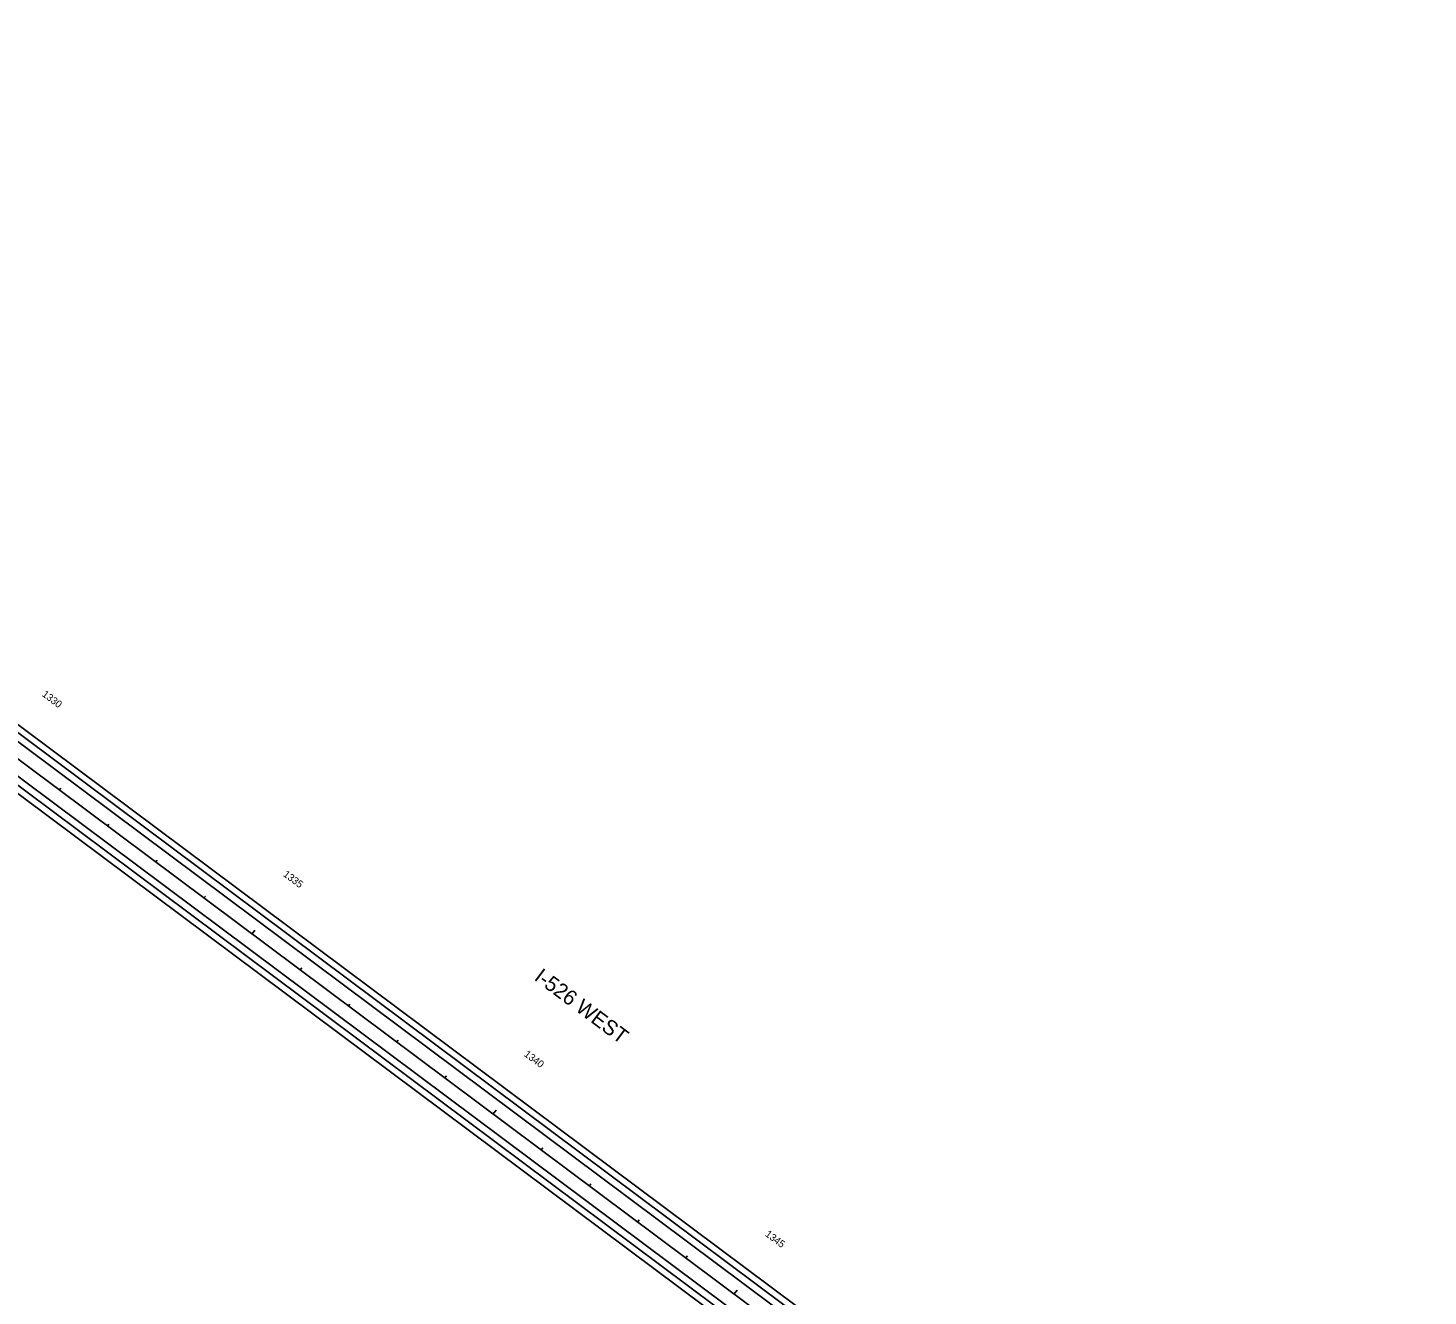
# Model space of a CAD drawing. Extents: x 2338610 to 2351914, y 366540 to 376484.
# Drawn here: x 2340895 to 2343223, y 372950 to 375057 of the extents above; entities that cross this region are included whole.
import ezdxf

# ---------------------------------------------------------------- set-up
doc = ezdxf.new("R2010")
doc.units = 0
for name, color, linetype in [('RD_HC_Cl', 7, 'Continuous'), ('RD_PD_Final_LnLine', 7, 'Continuous'), ('RD_PD_Final_TrvlWay', 7, 'Continuous'), ('TR SN UNASSIGNED 4', 7, 'Continuous'), ('TR SN UNASSIGNED 7', 7, 'Continuous')]:
    doc.layers.add(name, color=color, linetype=linetype)

msp = doc.modelspace()

# ---------------------------------------------------------------- linework, layer by layer
at = {"layer": 'RD_HC_Cl'}
msp.add_line((2339299.7, 375020.3), (2345298.7, 370542.8), dxfattribs=at)
at = {"layer": 'RD_PD_Final_LnLine'}
for p, q in [((2343497.3, 371916.1), (2339313.4, 375038.8)), ((2343504.5, 371925.7), (2339320.6, 375048.4)), ((2339278.7, 374992.3), (2343462.6, 371869.6)), ((2339285.9, 375001.9), (2343469.8, 371879.2))]:
    msp.add_line(p, q, dxfattribs=at)
at = {"layer": 'RD_PD_Final_TrvlWay'}
for p, q in [((2343458.6, 371973.7), (2339327.2, 375057.2)), ((2339272.2, 374983.5), (2343456.1, 371860.8))]:
    msp.add_line(p, q, dxfattribs=at)
at = {"layer": 'TR SN UNASSIGNED 7'}
for p, q in [((2340947.1, 373790.7), (2340949.5, 373793.9)), ((2341027.3, 373730.9), (2341029.7, 373734.1)), ((2341107.4, 373671.1), (2341109.8, 373674.3)), ((2341187.6, 373611.3), (2341190, 373614.5)), ((2341267.7, 373551.5), (2341272.5, 373557.9)), ((2341347.8, 373491.7), (2341350.2, 373494.9)), ((2341428, 373431.8), (2341430.4, 373435)), ((2341508.1, 373372), (2341510.5, 373375.2)), ((2341588.3, 373312.2), (2341590.7, 373315.4)), ((2341668.4, 373252.4), (2341673.2, 373258.8)), ((2341748.5, 373192.6), (2341750.9, 373195.8)), ((2341828.7, 373132.8), (2341831.1, 373136)), ((2341908.8, 373073), (2341911.2, 373076.2)), ((2341989, 373013.1), (2341991.4, 373016.4)), ((2342069.1, 372953.3), (2342073.9, 372959.7))]:
    msp.add_line(p, q, dxfattribs=at)

# ---------------------------------------------------------------- texts
at = {"layer": 'TR SN UNASSIGNED 4'}
msp.add_text('I-526 WEST', height=25, rotation=323.2637, dxfattribs=at).set_placement((2341735.2, 373476.1))
at = {"layer": 'TR SN UNASSIGNED 7'}
for s, p in [('1330', (2340917.4, 373947.7)), ('1335', (2341318.3, 373648.5)), ('1340', (2341718.8, 373349.5)), ('1345', (2342119.6, 373050.4))]:
    msp.add_text(s, height=12, rotation=323.2637, dxfattribs=at).set_placement(p)

doc.saveas('drawing.dxf')
